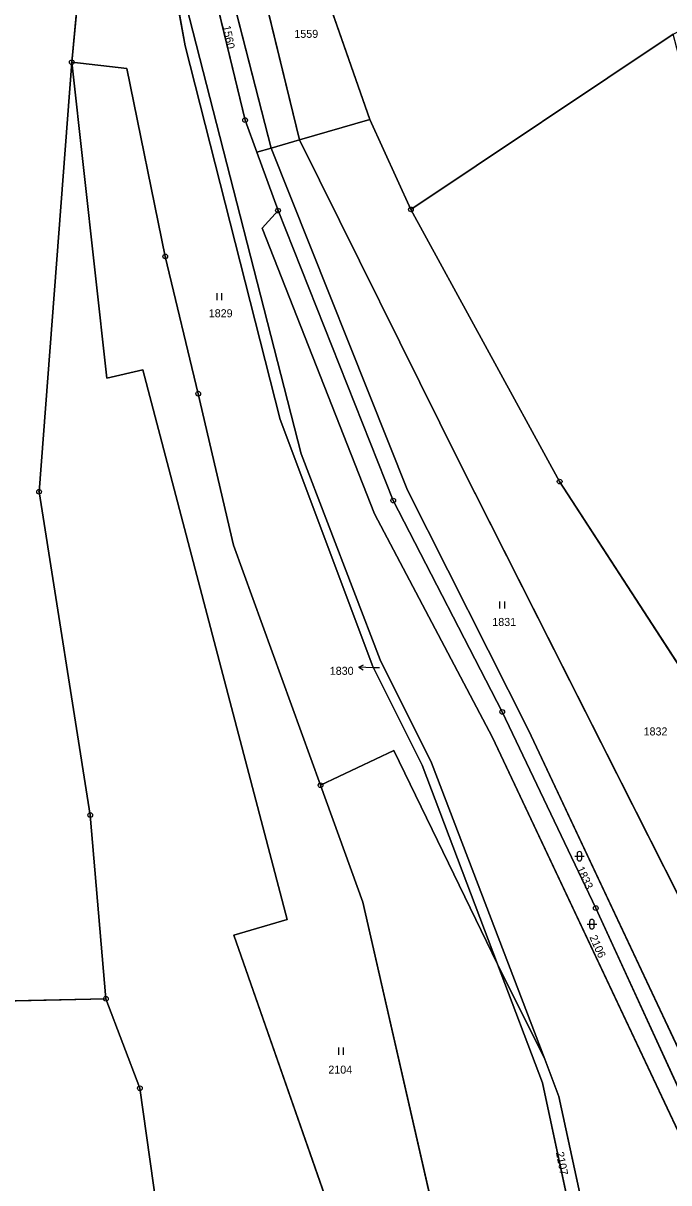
# Model space of a CAD drawing. Extents: x -689422 to -685210, y -987725 to -982160.
# Drawn here: x -687815.4 to -687678.3, y -986426 to -986179.8 of the extents above; entities that cross this region are included whole.
import ezdxf

# ---------------------------------------------------------------- set-up
doc = ezdxf.new("R2010")
doc.units = 0
for name, color, linetype in [('KN_Hranice_parcel', 7, 'Continuous'), ('KN_Parcelni cisla', 7, 'Continuous'), ('KN_Parcelni cisla_sipky', 7, 'Continuous'), ('KN_Polygon parcely', 7, 'Continuous'), ('KN_POZEMKY_LESNI POZEMEK', 7, 'Continuous'), ('KN_POZEMKY_ORNA PUDA', 7, 'Continuous'), ('KN_POZEMKY_OSTATNI PLOCHA', 7, 'Continuous'), ('KN_POZEMKY_TTP', 7, 'Continuous'), ('KN_VYUZITI_17_ostatni plocha_ostatni komunikace', 7, 'Continuous'), ('KN_VYUZITI_23_ostatni plocha_manipulacni plocha', 7, 'Continuous'), ('KN_VYUZITI_27_ostatni plocha_neplodna puda', 7, 'Continuous'), ('KN_Značky bodu BP', 7, 'Continuous'), ('KN_Značky kultur', 7, 'Continuous')]:
    doc.layers.add(name, color=color, linetype=linetype)

msp = doc.modelspace()

# ---------------------------------------------------------------- linework, layer by layer
at = {"layer": 'KN_Hranice_parcel'}
for p, q in [((-687733.06, -986219.3), (-687677.41, -986182.08)), ((-687768.29, -986200.34), (-687765.8, -986207.18)), ((-687756.7, -986204.55), (-687741.76, -986200.23)), ((-687741.76, -986200.23), (-687733.06, -986219.3)), ((-687762.74, -986206.3), (-687756.7, -986204.55)), ((-687765.8, -986207.18), (-687762.74, -986206.3)), ((-687765.8, -986207.18), (-687761.29, -986219.56)), ((-687785.22, -986229.28), (-687778.23, -986258.43)), ((-687714.68, -986379.59), (-687704.67, -986399.71)), ((-687864.46, -986388.44), (-687797.83, -986386.92))]:
    msp.add_line(p, q, dxfattribs=at)
for points in [[(-687756.7, -986204.55), (-687766.14, -986165.89), (-687762.36, -986150.03), (-687778.25, -986099.91), (-687791.66, -986043.39)], [(-687791.66, -986043.39), (-687774.85, -986096.33), (-687756.01, -986159.48), (-687741.76, -986200.23)], [(-687704.67, -986399.71), (-687728.71, -986336.82), (-687739.59, -986314.93), (-687756.39, -986271.2), (-687780.81, -986175.95), (-687792.52, -986091.55)], [(-687805.09, -986188.05), (-687799.7, -986131.22), (-687795.83, -986103.69)], [(-687714.68, -986379.59), (-687730.65, -986337.34), (-687741.14, -986316.36), (-687760.86, -986263.94), (-687780.97, -986184.55), (-687795.83, -986103.69)], [(-687784.66, -986118.51), (-687773.27, -986165.17), (-687762.74, -986206.3)], [(-687784.66, -986118.51), (-687776.6, -986165.78), (-687768.29, -986200.34)], [(-687797.83, -986386.92), (-687801.17, -986347.9), (-687812.02, -986279.24), (-687805.09, -986188.05)], [(-687805.09, -986188.05), (-687797.65, -986255.17), (-687790, -986253.39), (-687759.36, -986370.08), (-687770.7, -986373.38), (-687750.35, -986431.59), (-687746.52, -986430.63), (-687735.67, -986566.76), (-687730.88, -986571), (-687728.99, -986648.21), (-687717.65, -986667.57)], [(-687805.09, -986188.05), (-687793.42, -986189.36), (-687785.22, -986229.28)], [(-687666.18, -986419.01), (-687656.04, -986405.13), (-687722.66, -986273.21), (-687756.7, -986204.55)], [(-687762.74, -986206.3), (-687733.81, -986278.9), (-687708.11, -986329.88), (-687666.18, -986419.01)], [(-687761.29, -986219.56), (-687764.64, -986223.28), (-687740.77, -986283.94), (-687715.75, -986331.41), (-687667.6, -986433.6), (-687646.13, -986490.88), (-687635.98, -986531.01)], [(-687761.29, -986219.56), (-687736.81, -986281.12), (-687713.67, -986326.01), (-687693.82, -986367.67), (-687669.44, -986420.75)], [(-687626.46, -986398.61), (-687655.54, -986348.03), (-687701.49, -986277.08), (-687733.06, -986219.3)], [(-687778.23, -986258.43), (-687770.72, -986290.57), (-687752.26, -986341.57)], [(-687752.26, -986341.57), (-687736.7, -986334.17), (-687714.68, -986379.59)], [(-687716.8, -986482.2), (-687743.28, -986366.37), (-687752.26, -986341.57)], [(-687714.68, -986379.59), (-687705.16, -986404.79), (-687697.6, -986439.87), (-687684.56, -986454.06)], [(-687797.83, -986386.92), (-687790.62, -986405.91), (-687786.34, -986436.56), (-687784.88, -986471.18), (-687789.17, -986524.19), (-687787.49, -986570.08)], [(-687684.56, -986454.06), (-687685.97, -986448.79), (-687694.77, -986439.39), (-687701.66, -986407.66), (-687704.67, -986399.71)]]:
    msp.add_lwpolyline(points, dxfattribs=at)
at = {"layer": 'KN_Parcelni cisla_sipky'}
for p, q in [((-687744.16, -986316.51), (-687743.14, -986316.04)), ((-687741.16, -986316.61), (-687744.16, -986316.51)), ((-687744.16, -986316.51), (-687743.18, -986317.04)), ((-687739.72, -986316.65), (-687741.16, -986316.61))]:
    msp.add_line(p, q, dxfattribs=at)
at = {"layer": 'KN_Polygon parcely'}
for points in [[(-687864.46, -986388.44), (-687797.83, -986386.92), (-687801.17, -986347.9), (-687812.02, -986279.24), (-687805.09, -986188.05), (-687799.7, -986131.22), (-687795.83, -986103.69), (-687797.45, -986091.96), (-687799.44, -986053.43), (-687796.24, -986030.75), (-687817.51, -986032.37), (-687823.88, -986050.9), (-687827.17, -986077.3), (-687831.58, -986121.26), (-687837.55, -986175.06), (-687848.11, -986250.3), (-687857.26, -986327.29)], [(-687756.01, -986159.48), (-687741.76, -986200.23), (-687733.06, -986219.3), (-687677.41, -986182.08), (-687669.81, -986178.19), (-687694, -986159.36), (-687713.57, -986137.84), (-687742.87, -986096.76), (-687763.09, -986061.67), (-687773.55, -986049.34), (-687785.71, -986038.48), (-687791.66, -986043.39), (-687774.85, -986096.33)], [(-687778.25, -986099.91), (-687791.66, -986043.39), (-687795.01, -986054.51), (-687792.52, -986091.55), (-687784.66, -986118.51), (-687773.27, -986165.17), (-687762.74, -986206.3), (-687756.7, -986204.55), (-687766.14, -986165.89), (-687762.36, -986150.03)], [(-687741.76, -986200.23), (-687756.01, -986159.48), (-687774.85, -986096.33), (-687791.66, -986043.39), (-687778.25, -986099.91), (-687762.36, -986150.03), (-687766.14, -986165.89), (-687756.7, -986204.55)], [(-687728.71, -986336.82), (-687739.59, -986314.93), (-687756.39, -986271.2), (-687780.81, -986175.95), (-687792.52, -986091.55), (-687795.83, -986103.69), (-687780.97, -986184.55), (-687760.86, -986263.94), (-687741.14, -986316.36), (-687730.65, -986337.34), (-687714.68, -986379.59), (-687704.67, -986399.71)], [(-687644.64, -986534.13), (-687635.98, -986531.01), (-687646.13, -986490.88), (-687667.6, -986433.6), (-687715.75, -986331.41), (-687740.77, -986283.94), (-687764.64, -986223.28), (-687761.29, -986219.56), (-687765.8, -986207.18), (-687768.29, -986200.34), (-687776.6, -986165.78), (-687784.66, -986118.51), (-687792.52, -986091.55), (-687780.81, -986175.95), (-687756.39, -986271.2), (-687739.59, -986314.93), (-687728.71, -986336.82), (-687704.67, -986399.71), (-687701.66, -986407.66), (-687694.77, -986439.39), (-687685.97, -986448.79), (-687684.56, -986454.06), (-687677.72, -986489.86), (-687665.58, -986541.68)], [(-687778.23, -986258.43), (-687770.72, -986290.57), (-687752.26, -986341.57), (-687736.7, -986334.17), (-687714.68, -986379.59), (-687730.65, -986337.34), (-687741.14, -986316.36), (-687760.86, -986263.94), (-687780.97, -986184.55), (-687795.83, -986103.69), (-687799.7, -986131.22), (-687805.09, -986188.05), (-687793.42, -986189.36), (-687785.22, -986229.28)], [(-687765.8, -986207.18), (-687762.74, -986206.3), (-687773.27, -986165.17), (-687784.66, -986118.51), (-687776.6, -986165.78), (-687768.29, -986200.34)], [(-687565.07, -986490.79), (-687576.01, -986466.68), (-687596.22, -986412.38), (-687622.77, -986339.51), (-687633.58, -986343.39), (-687644.92, -986306.42), (-687656.43, -986262), (-687677.41, -986182.08), (-687733.06, -986219.3), (-687701.49, -986277.08), (-687655.54, -986348.03), (-687626.46, -986398.61), (-687576.47, -986510.61)], [(-687790.62, -986405.91), (-687786.34, -986436.56), (-687784.88, -986471.18), (-687789.17, -986524.19), (-687787.49, -986570.08), (-687786.3, -986578.26), (-687781.9, -986608.47), (-687722.74, -986669.66), (-687718.6, -986669.11), (-687717.65, -986667.57), (-687728.99, -986648.21), (-687730.88, -986571), (-687735.67, -986566.76), (-687746.52, -986430.63), (-687750.35, -986431.59), (-687770.7, -986373.38), (-687759.36, -986370.08), (-687790, -986253.39), (-687797.65, -986255.17), (-687805.09, -986188.05), (-687812.02, -986279.24), (-687801.17, -986347.9), (-687797.83, -986386.92)], [(-687730.88, -986571), (-687728.99, -986648.21), (-687717.65, -986667.57), (-687709, -986653.54), (-687710.27, -986635.88), (-687716.6, -986590.85), (-687718.81, -986555.38), (-687711.3, -986513.54), (-687716.8, -986482.2), (-687743.28, -986366.37), (-687752.26, -986341.57), (-687770.72, -986290.57), (-687778.23, -986258.43), (-687785.22, -986229.28), (-687793.42, -986189.36), (-687805.09, -986188.05), (-687797.65, -986255.17), (-687790, -986253.39), (-687759.36, -986370.08), (-687770.7, -986373.38), (-687750.35, -986431.59), (-687746.52, -986430.63), (-687735.67, -986566.76)], [(-687666.18, -986419.01), (-687626.46, -986398.61), (-687655.54, -986348.03), (-687701.49, -986277.08), (-687733.06, -986219.3), (-687741.76, -986200.23), (-687756.7, -986204.55), (-687722.66, -986273.21), (-687656.04, -986405.13)], [(-687708.11, -986329.88), (-687666.18, -986419.01), (-687656.04, -986405.13), (-687722.66, -986273.21), (-687756.7, -986204.55), (-687762.74, -986206.3), (-687733.81, -986278.9)], [(-687713.67, -986326.01), (-687693.82, -986367.67), (-687669.44, -986420.75), (-687666.18, -986419.01), (-687708.11, -986329.88), (-687733.81, -986278.9), (-687762.74, -986206.3), (-687765.8, -986207.18), (-687761.29, -986219.56), (-687736.81, -986281.12)], [(-687641.19, -986492.21), (-687669.44, -986420.75), (-687693.82, -986367.67), (-687713.67, -986326.01), (-687736.81, -986281.12), (-687761.29, -986219.56), (-687764.64, -986223.28), (-687740.77, -986283.94), (-687715.75, -986331.41), (-687667.6, -986433.6), (-687646.13, -986490.88), (-687635.98, -986531.01), (-687629.94, -986529.26)], [(-687705.4, -986480.6), (-687697.4, -986512.8), (-687685.8, -986587.5), (-687652.93, -986582.81), (-687649.44, -986617.42), (-687646.15, -986617.22), (-687653.18, -986562.91), (-687640.98, -986563.86), (-687644.64, -986534.13), (-687665.58, -986541.68), (-687677.72, -986489.86), (-687684.56, -986454.06), (-687697.6, -986439.87), (-687705.16, -986404.79), (-687714.68, -986379.59), (-687736.7, -986334.17), (-687752.26, -986341.57), (-687743.28, -986366.37), (-687716.8, -986482.2)], [(-687694.77, -986439.39), (-687701.66, -986407.66), (-687704.67, -986399.71), (-687714.68, -986379.59), (-687705.16, -986404.79), (-687697.6, -986439.87), (-687684.56, -986454.06), (-687685.97, -986448.79)], [(-687871.04, -986468.74), (-687876.41, -986536.11), (-687884.88, -986561.12), (-687886.23, -986565.1), (-687786.3, -986578.26), (-687787.49, -986570.08), (-687789.17, -986524.19), (-687784.88, -986471.18), (-687786.34, -986436.56), (-687790.62, -986405.91), (-687797.83, -986386.92), (-687864.46, -986388.44), (-687867.38, -986407.55), (-687869.16, -986432.27)]]:
    msp.add_lwpolyline(points, close=True, dxfattribs=at)
at = {"layer": 'KN_POZEMKY_LESNI POZEMEK'}
for p, q in [((-687812.02, -986279.24), (-687805.09, -986188.05)), ((-687805.09, -986188.05), (-687797.65, -986255.17)), ((-687797.65, -986255.17), (-687790, -986253.39)), ((-687790, -986253.39), (-687759.36, -986370.08)), ((-687801.17, -986347.9), (-687812.02, -986279.24)), ((-687797.83, -986386.92), (-687801.17, -986347.9)), ((-687759.36, -986370.08), (-687770.7, -986373.38)), ((-687770.7, -986373.38), (-687750.35, -986431.59)), ((-687790.62, -986405.91), (-687797.83, -986386.92)), ((-687786.34, -986436.56), (-687790.62, -986405.91))]:
    msp.add_line(p, q, dxfattribs=at)
at = {"layer": 'KN_POZEMKY_ORNA PUDA'}
for p, q in [((-687741.76, -986200.23), (-687756.01, -986159.48)), ((-687733.06, -986219.3), (-687677.41, -986182.08)), ((-687677.41, -986182.08), (-687733.06, -986219.3)), ((-687733.06, -986219.3), (-687741.76, -986200.23)), ((-687701.49, -986277.08), (-687733.06, -986219.3)), ((-687655.54, -986348.03), (-687701.49, -986277.08))]:
    msp.add_line(p, q, dxfattribs=at)
at = {"layer": 'KN_POZEMKY_OSTATNI PLOCHA'}
for p, q in [((-687780.97, -986184.55), (-687795.83, -986103.69)), ((-687756.01, -986159.48), (-687741.76, -986200.23)), ((-687768.29, -986200.34), (-687776.6, -986165.78)), ((-687773.27, -986165.17), (-687762.74, -986206.3)), ((-687756.7, -986204.55), (-687766.14, -986165.89)), ((-687780.81, -986175.95), (-687756.39, -986271.2)), ((-687760.86, -986263.94), (-687780.97, -986184.55)), ((-687765.8, -986207.18), (-687768.29, -986200.34)), ((-687756.7, -986204.55), (-687741.76, -986200.23)), ((-687741.76, -986200.23), (-687756.7, -986204.55)), ((-687741.76, -986200.23), (-687733.06, -986219.3)), ((-687722.66, -986273.21), (-687756.7, -986204.55)), ((-687765.8, -986207.18), (-687762.74, -986206.3)), ((-687762.74, -986206.3), (-687765.8, -986207.18)), ((-687761.29, -986219.56), (-687765.8, -986207.18)), ((-687762.74, -986206.3), (-687733.81, -986278.9)), ((-687764.64, -986223.28), (-687761.29, -986219.56)), ((-687761.29, -986219.56), (-687736.81, -986281.12)), ((-687736.81, -986281.12), (-687761.29, -986219.56)), ((-687733.06, -986219.3), (-687701.49, -986277.08)), ((-687740.77, -986283.94), (-687764.64, -986223.28)), ((-687741.14, -986316.36), (-687760.86, -986263.94)), ((-687756.39, -986271.2), (-687739.59, -986314.93)), ((-687656.04, -986405.13), (-687722.66, -986273.21)), ((-687733.81, -986278.9), (-687708.11, -986329.88)), ((-687701.49, -986277.08), (-687655.54, -986348.03)), ((-687736.81, -986281.12), (-687713.67, -986326.01)), ((-687713.67, -986326.01), (-687736.81, -986281.12)), ((-687715.75, -986331.41), (-687740.77, -986283.94)), ((-687739.59, -986314.93), (-687728.71, -986336.82)), ((-687730.65, -986337.34), (-687741.14, -986316.36)), ((-687713.67, -986326.01), (-687693.82, -986367.67)), ((-687693.82, -986367.67), (-687713.67, -986326.01)), ((-687708.11, -986329.88), (-687666.18, -986419.01)), ((-687667.6, -986433.6), (-687715.75, -986331.41)), ((-687714.68, -986379.59), (-687730.65, -986337.34)), ((-687728.71, -986336.82), (-687704.67, -986399.71)), ((-687693.82, -986367.67), (-687669.44, -986420.75)), ((-687669.44, -986420.75), (-687693.82, -986367.67)), ((-687705.16, -986404.79), (-687714.68, -986379.59)), ((-687714.68, -986379.59), (-687704.67, -986399.71)), ((-687704.67, -986399.71), (-687714.68, -986379.59)), ((-687704.67, -986399.71), (-687701.66, -986407.66)), ((-687697.6, -986439.87), (-687705.16, -986404.79)), ((-687701.66, -986407.66), (-687694.77, -986439.39))]:
    msp.add_line(p, q, dxfattribs=at)
at = {"layer": 'KN_POZEMKY_TTP'}
for p, q in [((-687795.83, -986103.69), (-687780.97, -986184.55)), ((-687799.7, -986131.22), (-687805.09, -986188.05)), ((-687805.09, -986188.05), (-687799.7, -986131.22)), ((-687776.6, -986165.78), (-687768.29, -986200.34)), ((-687762.74, -986206.3), (-687773.27, -986165.17)), ((-687766.14, -986165.89), (-687756.7, -986204.55)), ((-687756.39, -986271.2), (-687780.81, -986175.95)), ((-687780.97, -986184.55), (-687760.86, -986263.94)), ((-687805.09, -986188.05), (-687812.02, -986279.24)), ((-687797.65, -986255.17), (-687805.09, -986188.05)), ((-687805.09, -986188.05), (-687793.42, -986189.36)), ((-687793.42, -986189.36), (-687805.09, -986188.05)), ((-687793.42, -986189.36), (-687785.22, -986229.28)), ((-687785.22, -986229.28), (-687793.42, -986189.36)), ((-687768.29, -986200.34), (-687765.8, -986207.18)), ((-687762.74, -986206.3), (-687756.7, -986204.55)), ((-687756.7, -986204.55), (-687762.74, -986206.3)), ((-687756.7, -986204.55), (-687722.66, -986273.21)), ((-687765.8, -986207.18), (-687761.29, -986219.56)), ((-687733.81, -986278.9), (-687762.74, -986206.3)), ((-687761.29, -986219.56), (-687764.64, -986223.28)), ((-687764.64, -986223.28), (-687740.77, -986283.94)), ((-687785.22, -986229.28), (-687778.23, -986258.43)), ((-687778.23, -986258.43), (-687785.22, -986229.28)), ((-687790, -986253.39), (-687797.65, -986255.17)), ((-687759.36, -986370.08), (-687790, -986253.39)), ((-687778.23, -986258.43), (-687770.72, -986290.57)), ((-687770.72, -986290.57), (-687778.23, -986258.43)), ((-687760.86, -986263.94), (-687741.14, -986316.36)), ((-687739.59, -986314.93), (-687756.39, -986271.2)), ((-687722.66, -986273.21), (-687656.04, -986405.13)), ((-687812.02, -986279.24), (-687801.17, -986347.9)), ((-687708.11, -986329.88), (-687733.81, -986278.9)), ((-687740.77, -986283.94), (-687715.75, -986331.41)), ((-687770.72, -986290.57), (-687752.26, -986341.57)), ((-687752.26, -986341.57), (-687770.72, -986290.57)), ((-687728.71, -986336.82), (-687739.59, -986314.93)), ((-687741.14, -986316.36), (-687730.65, -986337.34)), ((-687666.18, -986419.01), (-687708.11, -986329.88)), ((-687715.75, -986331.41), (-687667.6, -986433.6)), ((-687752.26, -986341.57), (-687736.7, -986334.17)), ((-687736.7, -986334.17), (-687752.26, -986341.57)), ((-687736.7, -986334.17), (-687714.68, -986379.59)), ((-687714.68, -986379.59), (-687736.7, -986334.17)), ((-687730.65, -986337.34), (-687714.68, -986379.59)), ((-687704.67, -986399.71), (-687728.71, -986336.82)), ((-687743.28, -986366.37), (-687752.26, -986341.57)), ((-687752.26, -986341.57), (-687743.28, -986366.37)), ((-687801.17, -986347.9), (-687797.83, -986386.92)), ((-687716.8, -986482.2), (-687743.28, -986366.37)), ((-687743.28, -986366.37), (-687716.8, -986482.2)), ((-687770.7, -986373.38), (-687759.36, -986370.08)), ((-687750.35, -986431.59), (-687770.7, -986373.38)), ((-687714.68, -986379.59), (-687705.16, -986404.79)), ((-687864.46, -986388.44), (-687797.83, -986386.92)), ((-687797.83, -986386.92), (-687864.46, -986388.44)), ((-687797.83, -986386.92), (-687790.62, -986405.91)), ((-687701.66, -986407.66), (-687704.67, -986399.71)), ((-687705.16, -986404.79), (-687697.6, -986439.87)), ((-687790.62, -986405.91), (-687786.34, -986436.56)), ((-687694.77, -986439.39), (-687701.66, -986407.66))]:
    msp.add_line(p, q, dxfattribs=at)
at = {"layer": 'KN_VYUZITI_17_ostatni plocha_ostatni komunikace'}
for p, q in [((-687780.97, -986184.55), (-687795.83, -986103.69)), ((-687780.81, -986175.95), (-687756.39, -986271.2)), ((-687760.86, -986263.94), (-687780.97, -986184.55)), ((-687741.14, -986316.36), (-687760.86, -986263.94)), ((-687756.39, -986271.2), (-687739.59, -986314.93)), ((-687739.59, -986314.93), (-687728.71, -986336.82)), ((-687730.65, -986337.34), (-687741.14, -986316.36)), ((-687714.68, -986379.59), (-687730.65, -986337.34)), ((-687728.71, -986336.82), (-687704.67, -986399.71)), ((-687705.16, -986404.79), (-687714.68, -986379.59)), ((-687714.68, -986379.59), (-687704.67, -986399.71)), ((-687704.67, -986399.71), (-687714.68, -986379.59)), ((-687704.67, -986399.71), (-687701.66, -986407.66)), ((-687697.6, -986439.87), (-687705.16, -986404.79)), ((-687701.66, -986407.66), (-687694.77, -986439.39))]:
    msp.add_line(p, q, dxfattribs=at)
at = {"layer": 'KN_VYUZITI_23_ostatni plocha_manipulacni plocha'}
for p, q in [((-687756.7, -986204.55), (-687741.76, -986200.23)), ((-687741.76, -986200.23), (-687733.06, -986219.3)), ((-687722.66, -986273.21), (-687756.7, -986204.55)), ((-687733.06, -986219.3), (-687701.49, -986277.08)), ((-687656.04, -986405.13), (-687722.66, -986273.21)), ((-687701.49, -986277.08), (-687655.54, -986348.03))]:
    msp.add_line(p, q, dxfattribs=at)
at = {"layer": 'KN_VYUZITI_27_ostatni plocha_neplodna puda'}
for p, q in [((-687756.01, -986159.48), (-687741.76, -986200.23)), ((-687768.29, -986200.34), (-687776.6, -986165.78)), ((-687773.27, -986165.17), (-687762.74, -986206.3)), ((-687756.7, -986204.55), (-687766.14, -986165.89)), ((-687765.8, -986207.18), (-687768.29, -986200.34)), ((-687741.76, -986200.23), (-687756.7, -986204.55)), ((-687765.8, -986207.18), (-687762.74, -986206.3)), ((-687762.74, -986206.3), (-687765.8, -986207.18)), ((-687761.29, -986219.56), (-687765.8, -986207.18)), ((-687762.74, -986206.3), (-687733.81, -986278.9)), ((-687764.64, -986223.28), (-687761.29, -986219.56)), ((-687761.29, -986219.56), (-687736.81, -986281.12)), ((-687736.81, -986281.12), (-687761.29, -986219.56)), ((-687740.77, -986283.94), (-687764.64, -986223.28)), ((-687733.81, -986278.9), (-687708.11, -986329.88)), ((-687736.81, -986281.12), (-687713.67, -986326.01)), ((-687713.67, -986326.01), (-687736.81, -986281.12)), ((-687715.75, -986331.41), (-687740.77, -986283.94)), ((-687713.67, -986326.01), (-687693.82, -986367.67)), ((-687693.82, -986367.67), (-687713.67, -986326.01)), ((-687708.11, -986329.88), (-687666.18, -986419.01)), ((-687667.6, -986433.6), (-687715.75, -986331.41)), ((-687693.82, -986367.67), (-687669.44, -986420.75)), ((-687669.44, -986420.75), (-687693.82, -986367.67))]:
    msp.add_line(p, q, dxfattribs=at)
at = {"layer": 'KN_Značky bodu BP'}
for centre, radius in [((-687805.09, -986188.05), 0.5), ((-687805.09, -986188.05), 0.0303), ((-687768.29, -986200.34), 0.5), ((-687768.29, -986200.34), 0.0303), ((-687761.29, -986219.56), 0.5), ((-687761.29, -986219.56), 0.0303), ((-687733.06, -986219.3), 0.5), ((-687733.06, -986219.3), 0.0303), ((-687785.22, -986229.28), 0.5), ((-687785.22, -986229.28), 0.0303), ((-687778.23, -986258.43), 0.5), ((-687778.23, -986258.43), 0.0303), ((-687701.49, -986277.08), 0.5), ((-687812.02, -986279.24), 0.5), ((-687812.02, -986279.24), 0.0303), ((-687701.49, -986277.08), 0.0303), ((-687736.81, -986281.12), 0.5), ((-687736.81, -986281.12), 0.0303), ((-687713.67, -986326.01), 0.5), ((-687713.67, -986326.01), 0.0303), ((-687752.26, -986341.57), 0.5), ((-687752.26, -986341.57), 0.0303), ((-687801.17, -986347.9), 0.5), ((-687801.17, -986347.9), 0.0303), ((-687693.82, -986367.67), 0.5), ((-687693.82, -986367.67), 0.0303), ((-687797.83, -986386.92), 0.5), ((-687797.83, -986386.92), 0.0303), ((-687790.62, -986405.91), 0.5), ((-687790.62, -986405.91), 0.0303)]:
    msp.add_circle(centre, radius, dxfattribs=at)
at = {"layer": 'KN_Značky kultur'}
for p, q in [((-687774.24, -986238.59), (-687774.24, -986237.09)), ((-687773.24, -986238.59), (-687773.24, -986237.09)), ((-687714.16, -986304.04), (-687714.16, -986302.54)), ((-687713.16, -986304.04), (-687713.16, -986302.54)), ((-687698.28, -986356.65), (-687696.28, -986356.65)), ((-687697.78, -986356.15), (-687697.78, -986357.15)), ((-687696.78, -986357.15), (-687696.78, -986356.15)), ((-687695.63, -986371.08), (-687693.63, -986371.08)), ((-687695.13, -986370.58), (-687695.13, -986371.58)), ((-687694.13, -986371.58), (-687694.13, -986370.58)), ((-687748.39, -986398.79), (-687748.39, -986397.29)), ((-687747.39, -986398.79), (-687747.39, -986397.29))]:
    msp.add_line(p, q, dxfattribs=at)
for centre, start, end in [((-687697.28, -986356.15), 0, 180), ((-687697.28, -986357.15), 180, 359.9879), ((-687694.63, -986370.58), 0, 180), ((-687694.63, -986371.58), 180, 359.9879)]:
    msp.add_arc(centre, 0.5, start, end, dxfattribs=at)

# ---------------------------------------------------------------- texts
at = {"layer": 'KN_Parcelni cisla'}
for s, rotation, p in [('1560', 281, (-687773.05, -986180.38)), ('1833', 295, (-687697.97, -986359.28)), ('2106', 294, (-687695.21, -986373.83)), ('2107', 281, (-687702.3, -986419.55))]:
    msp.add_text(s, height=1.7, rotation=rotation, dxfattribs=at).set_placement(p)
for s, p in [('1559', (-687757.82, -986182.87)), ('1829', (-687775.99, -986242.2)), ('1831', (-687715.79, -986307.75)), ('1830', (-687750.3, -986318.13)), ('1832', (-687683.67, -986331)), ('2104', (-687750.6, -986402.81))]:
    msp.add_text(s, height=1.7, dxfattribs=at).set_placement(p)

doc.saveas('drawing.dxf')
